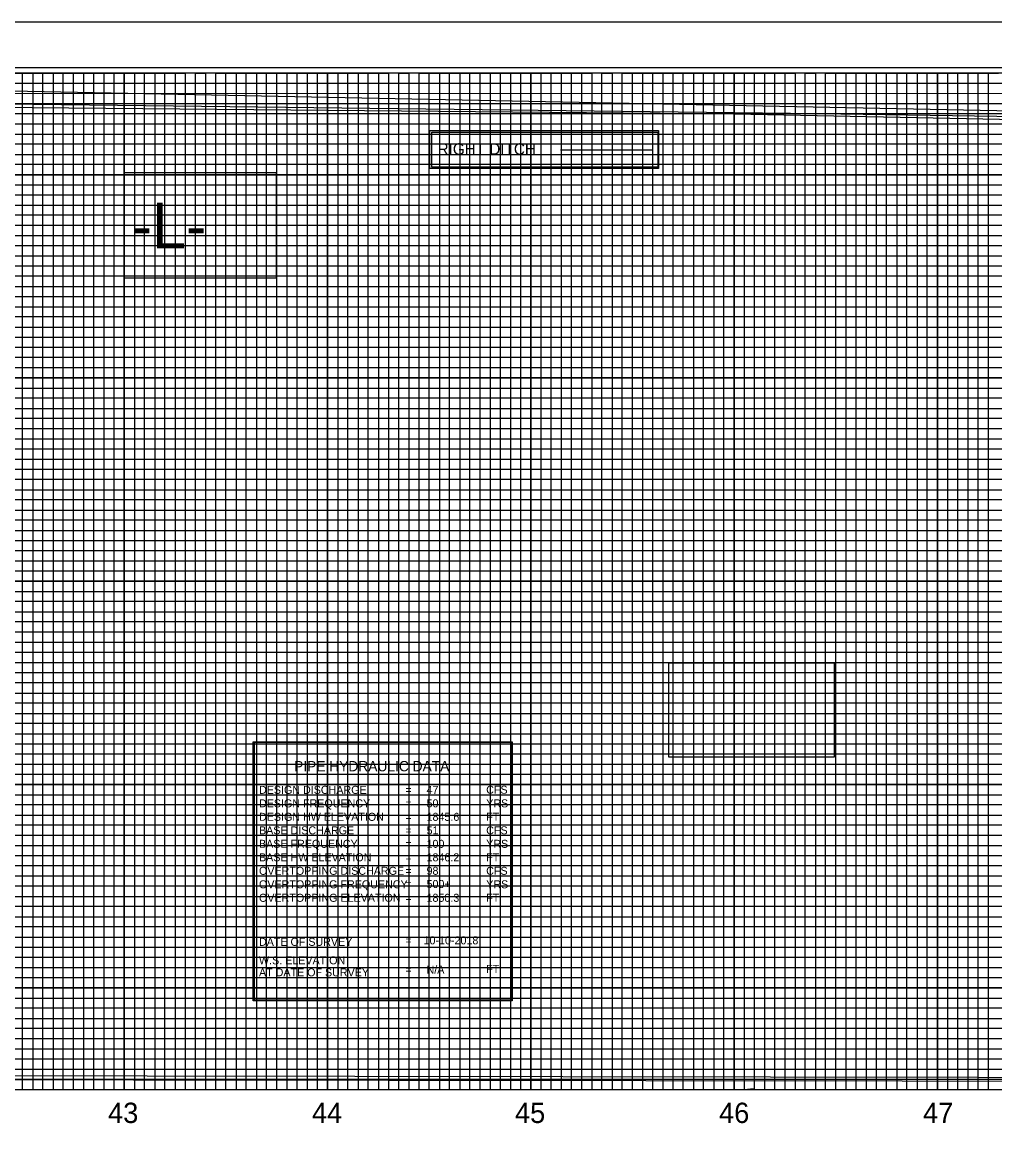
# Model space of a CAD drawing. Extents: x 557032 to 562069, y 513430 to 515874.
# Drawn here: x 557699 to 558178, y 515328 to 515874 of the extents above; entities that cross this region are included whole.
import ezdxf

# ---------------------------------------------------------------- set-up
doc = ezdxf.new("R2010")
doc.units = 0
for name, color, linetype in [('Exist Vertical Profile Horizontal Axis Label Major', 7, 'Continuous'), ('Prop Grid Mask', 7, 'Continuous'), ('Prop PFL Ditch Label CELL', 7, 'Continuous'), ('Prop Vertical Profile Curve Label', 7, 'Continuous'), ('Prop VPI Label', 7, 'Continuous'), ('Scratch_Level_5', 7, 'Continuous'), ('Sheet Cutting Line CELL', 7, 'Continuous'), ('Sheet DOT Grid CELL', 7, 'Continuous'), ('Sheet Layout Profile Border Port 1', 7, 'Continuous'), ('Sheet Plot Border Inside CELL', 7, 'Continuous'), ('Sheet Plot Border Outside CELL', 7, 'Continuous'), ('Sheet Profile CELL', 7, 'Continuous'), ('Sheet Profile Grid Major CELL', 7, 'Continuous'), ('Sheet Profile Grid Middle CELL', 7, 'Continuous'), ('Sheet Profile Grid Minor CELL', 7, 'Continuous')]:
    doc.layers.add(name, color=color, linetype=linetype)

msp = doc.modelspace()

# ---------------------------------------------------------------- linework, layer by layer
at = {"layer": 'Prop Grid Mask'}
msp.add_lwpolyline([(557899.83, 515821.03), (558012.33, 515821.03), (558012.33, 515802.28), (557899.83, 515802.28)], close=True, dxfattribs=at)
at = {"layer": 'Prop PFL Ditch Label CELL'}
for p, q in [((557899.83, 515809.78), (557899.83, 515809.78)), ((557963.99, 515811.54), (558008.99, 515811.54))]:
    msp.add_line(p, q, dxfattribs=at)
at = {"layer": 'Prop Vertical Profile Curve Label'}
for points in [[(557749.44, 515800.34), (557824.2, 515800.34), (557824.2, 515748.39), (557749.44, 515748.39)], [(557749.44, 515800.34), (557824.2, 515800.34), (557824.2, 515748.39), (557749.44, 515748.39)], [(558017.37, 515559.11), (558098.7, 515559.11), (558098.7, 515512.81), (558017.37, 515512.81)], [(557812.9, 515520.28), (557940.3, 515520.28), (557940.3, 515392.88), (557812.9, 515392.88)]]:
    msp.add_lwpolyline(points, close=True, dxfattribs=at)
at = {"layer": 'Prop VPI Label'}
for points in [[(557900.71, 515820.13), (558011.86, 515820.13), (558011.86, 515802.99), (557900.71, 515802.99)], [(557749.44, 515800.34), (557824.2, 515800.34), (557824.2, 515748.39), (557749.44, 515748.39)], [(557813.36, 515393.43), (557939.92, 515393.43), (557939.92, 515520), (557813.36, 515520)]]:
    msp.add_lwpolyline(points, close=True, dxfattribs=at)
at = {"layer": 'Scratch_Level_5'}
msp.add_lwpolyline([(558499.4, 515824.23), (557249.45, 515849.28), (557249.45, 515349.28), (557236.61, 515332.67), (557249.45, 515324.28), (558649.45, 515324.28), (558662.72, 515334.01), (558649.45, 515349.28), (558649.45, 515688.23), (558499.4, 515688.23)], close=True, dxfattribs=at)
for points in [[(558649.42, 515686.42), (558641.97, 515686.42), (558497.02, 515687.96), (558497.02, 515823.15), (558090.9, 515829.21), (557249.42, 515839.17)], [(558649.45, 515682.57), (558492.81, 515683.83), (558490.11, 515820.17), (558049.46, 515829.04), (557249.45, 515836.19)], [(557249.42, 515356.85), (558373.93, 515355.08), (558412.39, 515354.77), (558649.42, 515355.8)], [(557249.45, 515354.68), (558384.27, 515353.2), (558399.94, 515350.88), (558440.57, 515354.03), (558649.45, 515354.48)]]:
    msp.add_lwpolyline(points, dxfattribs=at)
at = {"layer": 'Sheet Cutting Line CELL'}
msp.add_line((558716.45, 515874.28), (557032.45, 515874.28), dxfattribs=at)
at = {"layer": 'Sheet DOT Grid CELL'}
for p, q in [((557699.45, 515349.28), (557699.45, 515849.28)), ((557749.45, 515349.28), (557749.45, 515849.28)), ((557799.45, 515349.28), (557799.45, 515849.28)), ((557849.45, 515349.28), (557849.45, 515849.28)), ((557899.45, 515349.28), (557899.45, 515849.28)), ((557949.45, 515349.28), (557949.45, 515849.28)), ((557999.45, 515349.28), (557999.45, 515849.28)), ((558049.45, 515349.28), (558049.45, 515849.28)), ((558099.45, 515349.28), (558099.45, 515849.28)), ((558149.45, 515349.28), (558149.45, 515849.28)), ((558499.4, 515799.28), (557199.45, 515799.28)), ((558499.4, 515749.28), (557199.45, 515749.28)), ((558499.45, 515699.28), (557199.45, 515699.28)), ((558699.45, 515649.28), (557199.45, 515649.28)), ((558699.45, 515599.28), (557199.45, 515599.28)), ((558699.45, 515549.28), (557199.45, 515549.28)), ((558699.45, 515499.28), (557199.45, 515499.28)), ((558699.45, 515449.28), (557199.45, 515449.28)), ((558699.45, 515399.28), (557199.45, 515399.28))]:
    msp.add_line(p, q, dxfattribs=at)
at = {"layer": 'Sheet Layout Profile Border Port 1'}
msp.add_lwpolyline([(557249.45, 515688.23), (557249.45, 515349.28), (558649.45, 515349.28), (558649.45, 515688.23)], dxfattribs=at)
at = {"layer": 'Sheet Plot Border Inside CELL'}
msp.add_lwpolyline([(557045.45, 514796.73), (558711.95, 514796.73), (558711.95, 515851.83), (557045.45, 515851.83)], close=True, dxfattribs=at)
at = {"layer": 'Sheet Plot Border Outside CELL'}
msp.add_lwpolyline([(557032.45, 514774.28), (558716.45, 514774.28), (558716.45, 515874.28), (557032.45, 515874.28)], close=True, dxfattribs=at)
at = {"layer": 'Sheet Profile CELL'}
msp.add_line((557199.45, 515349.28), (558699.45, 515349.28), dxfattribs=at)
msp.add_lwpolyline([(558699.45, 515849.28), (557199.45, 515849.28), (557199.45, 514799.28), (558699.45, 514799.28)], close=True, dxfattribs=at)
at = {"layer": 'Sheet Profile Grid Major CELL'}
for points in [[(557649.45, 515349.28), (557699.45, 515349.28), (557699.45, 515849.28), (557749.45, 515849.28), (557749.45, 515349.28), (557799.45, 515349.28), (557799.45, 515849.28), (557849.45, 515849.28), (557849.45, 515349.28), (557899.45, 515349.28), (557899.45, 515849.28), (557949.45, 515849.28), (557949.45, 515349.28), (557999.45, 515349.28), (557999.45, 515849.28), (558049.45, 515849.28), (558049.45, 515349.28), (558099.45, 515349.28), (558099.45, 515849.28), (558149.45, 515849.28), (558149.45, 515349.28), (558199.45, 515349.28)], [(557199.45, 515799.28), (558499.45, 515799.28)], [(558499.45, 515749.28), (557199.45, 515749.28), (557199.45, 515699.28), (558499.45, 515699.28)], [(558699.45, 515649.28), (557199.45, 515649.28), (557199.45, 515599.28), (558699.45, 515599.28)], [(558699.45, 515549.28), (557199.45, 515549.28), (557199.45, 515499.28), (558699.45, 515499.28)], [(558699.45, 515449.28), (557199.45, 515449.28), (557199.45, 515449.28), (557199.45, 515399.28), (558699.45, 515399.28)]]:
    msp.add_lwpolyline(points, dxfattribs=at)
at = {"layer": 'Sheet Profile Grid Middle CELL'}
msp.add_line((557199.45, 515824.28), (558499.4, 515824.28), dxfattribs=at)
for points in [[(557674.45, 515349.28), (557724.45, 515349.28), (557724.45, 515849.28), (557774.45, 515849.28), (557774.45, 515349.28), (557824.45, 515349.28), (557824.45, 515349.28), (557824.45, 515849.28), (557874.45, 515849.28), (557874.45, 515349.28), (557924.45, 515349.28), (557924.45, 515849.28), (557974.45, 515849.28), (557974.45, 515349.28), (558024.45, 515349.28), (558024.45, 515849.28), (558074.45, 515849.28), (558074.45, 515349.28), (558124.45, 515349.28), (558124.45, 515849.28), (558174.45, 515849.28), (558174.45, 515349.28), (558224.45, 515349.28)], [(558499.45, 515774.28), (557199.45, 515774.28), (557199.45, 515724.28), (558499.45, 515724.28)], [(558699.45, 515674.28), (557199.45, 515674.28), (557199.45, 515624.28), (558524.45, 515624.28)], [(558699.45, 515574.28), (557199.45, 515574.28), (557199.45, 515524.28), (558699.45, 515524.28)], [(558699.45, 515474.28), (557199.45, 515474.28), (557199.45, 515424.28), (558699.45, 515424.28)], [(558699.45, 515374.28), (557199.45, 515374.28)]]:
    msp.add_lwpolyline(points, dxfattribs=at)
at = {"layer": 'Sheet Profile Grid Minor CELL'}
for p, q in [((557249.45, 515844.28), (558499.45, 515844.28)), ((558499.45, 515839.28), (557249.45, 515838.93)), ((557249.45, 515834.28), (558499.45, 515834.28)), ((558499.4, 515714.28), (557249.45, 515714.28)), ((558499.45, 515709.28), (557249.45, 515709.28)), ((558499.45, 515704.28), (557249.45, 515704.28)), ((557249.45, 515694.28), (558499.45, 515694.28)), ((558499.45, 515689.28), (557249.45, 515689.28)), ((557249.45, 515684.28), (558649.45, 515684.28)), ((558649.45, 515664.28), (557249.45, 515664.28)), ((557249.45, 515659.28), (558649.45, 515659.28)), ((558649.45, 515639.28), (557249.45, 515639.28)), ((557249.45, 515634.28), (558649.45, 515634.28)), ((558649.45, 515614.28), (557249.45, 515614.28)), ((557249.45, 515609.28), (558649.45, 515609.28)), ((558649.45, 515604.28), (557249.45, 515604.28)), ((557249.45, 515594.28), (558649.45, 515594.28)), ((558649.45, 515589.28), (557249.45, 515589.28)), ((557249.45, 515584.28), (558649.45, 515584.28)), ((558649.45, 515579.28), (557249.45, 515579.28)), ((557249.45, 515569.28), (558649.45, 515569.28)), ((558649.45, 515564.28), (557249.45, 515564.28)), ((557249.45, 515559.28), (558649.45, 515559.28)), ((558649.45, 515554.28), (557249.45, 515554.28)), ((557249.45, 515544.28), (558649.45, 515544.28)), ((558649.45, 515539.28), (557249.45, 515539.28)), ((557249.45, 515534.28), (558649.45, 515534.28)), ((558649.45, 515529.28), (557249.45, 515529.28)), ((557249.45, 515519.28), (558649.45, 515519.28)), ((558649.45, 515514.28), (557249.45, 515514.28)), ((557249.45, 515509.28), (558649.45, 515509.28)), ((558649.45, 515504.28), (557249.45, 515504.28)), ((557249.45, 515494.28), (558649.45, 515494.28)), ((558649.45, 515489.28), (557249.45, 515489.28)), ((557249.45, 515484.28), (558649.45, 515484.28)), ((558649.45, 515479.28), (557249.45, 515479.28)), ((557249.45, 515469.28), (558649.45, 515469.28)), ((558649.45, 515464.28), (557249.45, 515464.28)), ((558649.45, 515459.28), (557249.45, 515459.28)), ((558649.45, 515454.28), (557249.45, 515454.28)), ((557249.45, 515444.28), (558649.45, 515444.28)), ((558649.45, 515439.28), (557249.45, 515439.28)), ((557249.45, 515434.28), (558649.45, 515434.28)), ((558649.45, 515429.28), (557249.45, 515429.28)), ((557249.45, 515419.28), (558649.45, 515419.28)), ((558649.45, 515414.28), (557249.45, 515414.28)), ((557249.45, 515409.28), (558649.45, 515409.28)), ((558649.45, 515404.28), (557249.45, 515404.28)), ((557249.45, 515394.28), (558649.45, 515394.28)), ((558649.45, 515389.28), (557249.45, 515389.28)), ((557249.45, 515384.28), (558649.45, 515384.28)), ((558649.45, 515379.28), (557249.45, 515379.28)), ((557249.45, 515369.28), (558649.45, 515369.28)), ((558649.45, 515364.28), (557249.45, 515364.28)), ((557249.45, 515359.28), (558649.45, 515359.28))]:
    msp.add_line(p, q, dxfattribs=at)
for points in [[(557694.45, 515849.28), (557704.45, 515849.28), (557704.45, 515349.28), (557709.45, 515349.28), (557709.45, 515849.28), (557714.45, 515849.28), (557714.45, 515349.28), (557719.45, 515349.28), (557719.45, 515849.28), (557729.45, 515849.28), (557729.45, 515349.28), (557734.45, 515349.28), (557734.45, 515849.28), (557739.45, 515849.28), (557739.45, 515349.28), (557744.45, 515349.28), (557744.45, 515849.28), (557754.45, 515849.28), (557754.45, 515349.28), (557759.45, 515349.28), (557759.45, 515849.28), (557764.45, 515849.28), (557764.45, 515349.28), (557769.45, 515349.28), (557769.45, 515849.28), (557779.45, 515849.28)], [(557779.45, 515849.28), (557779.45, 515349.28), (557784.45, 515349.28), (557784.45, 515849.28), (557789.45, 515849.28), (557789.45, 515349.28), (557794.45, 515349.28), (557794.45, 515849.28), (557804.45, 515849.28), (557804.45, 515349.28), (557809.45, 515349.28), (557809.45, 515849.28), (557814.45, 515849.28), (557814.45, 515349.28), (557819.45, 515349.28), (557819.45, 515849.28), (557829.45, 515849.28), (557829.45, 515349.28), (557834.45, 515349.28), (557834.45, 515849.28), (557839.45, 515849.28), (557839.45, 515349.28), (557844.45, 515349.28), (557844.45, 515849.28), (557854.45, 515849.28), (557854.45, 515349.28), (557859.45, 515349.28), (557859.45, 515849.28), (557864.45, 515849.28), (557864.45, 515349.28), (557869.45, 515349.28), (557869.45, 515849.28), (557879.45, 515849.28), (557879.45, 515349.28), (557884.45, 515349.28), (557884.45, 515849.28), (557889.45, 515849.28), (557889.45, 515349.28), (557894.45, 515349.28), (557894.45, 515849.28), (557904.45, 515849.28), (557904.45, 515349.28), (557904.45, 515349.28), (557909.45, 515349.28), (557909.45, 515849.28), (557914.45, 515849.28), (557914.45, 515349.28), (557919.45, 515349.28), (557919.45, 515849.28), (557929.45, 515849.28), (557929.45, 515349.28), (557934.45, 515349.28), (557934.45, 515849.28), (557939.45, 515849.28), (557939.45, 515349.28), (557944.45, 515349.28), (557944.45, 515849.28), (557954.45, 515849.28), (557954.45, 515349.28), (557959.45, 515349.28), (557959.45, 515849.28), (557964.45, 515849.28), (557964.45, 515349.28), (557969.45, 515349.28), (557969.45, 515849.28), (557979.45, 515849.28), (557979.45, 515349.28), (557984.45, 515349.28), (557984.45, 515849.28), (557989.45, 515849.28), (557989.45, 515349.28), (557994.45, 515349.28), (557994.45, 515849.28), (558004.45, 515849.28), (558004.45, 515349.28), (558009.45, 515349.28), (558009.45, 515849.28), (558014.45, 515849.28), (558014.45, 515349.28), (558019.45, 515349.28), (558019.45, 515849.28), (558029.45, 515849.28), (558029.45, 515349.28), (558034.45, 515349.28), (558034.45, 515849.28), (558039.45, 515849.28), (558039.45, 515349.28), (558044.45, 515349.28), (558044.45, 515849.28), (558054.45, 515849.28), (558054.45, 515349.28), (558059.15, 515349.83), (558059.45, 515349.28), (558059.45, 515849.28), (558064.45, 515849.28), (558064.45, 515349.28), (558069.45, 515349.28), (558069.45, 515849.28), (558079.45, 515849.28), (558079.45, 515349.28), (558084.45, 515349.28)], [(558084.45, 515349.28), (558084.45, 515849.28), (558089.45, 515849.28), (558089.45, 515349.28), (558094.45, 515349.28), (558094.45, 515849.28), (558104.45, 515849.28), (558104.45, 515349.28), (558109.45, 515349.28), (558109.45, 515849.28), (558114.45, 515849.28), (558114.45, 515349.28), (558119.45, 515349.28), (558119.45, 515849.28), (558129.45, 515849.28), (558129.45, 515349.28), (558134.45, 515349.28), (558134.45, 515849.28), (558139.45, 515849.28), (558139.45, 515349.28), (558144.45, 515349.28), (558144.45, 515849.28), (558154.45, 515849.28), (558154.45, 515349.28), (558159.45, 515349.28), (558159.45, 515849.28), (558164.45, 515849.28), (558164.45, 515349.28), (558169.45, 515349.28), (558169.45, 515849.28), (558179.45, 515849.28)], [(558499.45, 515829.28), (557249.45, 515829.28), (557249.45, 515819.28), (558499.45, 515819.28)], [(558499.4, 515814.28), (557249.45, 515814.28), (557249.45, 515809.28), (558499.45, 515809.28)], [(558499.45, 515804.28), (557249.45, 515804.28), (557249.45, 515794.28), (558499.45, 515794.28)], [(558499.45, 515789.28), (557249.45, 515789.28), (557249.45, 515784.28), (558499.45, 515784.28)], [(558499.45, 515779.28), (557249.45, 515779.28), (557249.45, 515769.28), (558499.45, 515769.28)], [(558499.45, 515764.28), (557249.45, 515764.28), (557249.45, 515759.28), (558499.45, 515759.28)], [(558499.45, 515754.28), (557249.45, 515754.28), (557249.45, 515744.28), (558499.45, 515744.28)], [(558499.45, 515739.18), (557249.55, 515739.18), (557249.55, 515734.28), (558499.45, 515734.28)], [(558499.45, 515729.28), (557249.45, 515729.28), (557249.45, 515719.28), (558499.45, 515719.28)], [(558649.45, 515679.28), (557249.45, 515679.28), (557249.45, 515669.28), (558649.45, 515669.28)], [(558649.45, 515654.28), (557249.45, 515654.28), (557249.45, 515644.28), (558649.45, 515644.28)], [(558649.45, 515629.28), (557249.45, 515629.28), (557249.45, 515619.28), (558649.45, 515619.28)], [(558649.45, 515354.28), (557249.45, 515354.28)]]:
    msp.add_lwpolyline(points, dxfattribs=at)

# ---------------------------------------------------------------- texts
at = {"layer": 'Exist Vertical Profile Horizontal Axis Label Major'}
for s, p in [('43', (557741.46, 515332.81)), ('44', (557841.76, 515332.81)), ('45', (557941.65, 515332.81)), ('46', (558042.04, 515332.81)), ('47', (558142.39, 515332.81))]:
    msp.add_text(s, height=10, dxfattribs=at).set_placement(p)
at = {"layer": 'Prop PFL Ditch Label CELL'}
msp.add_text('RIGHT DITCH', height=5.6138, dxfattribs=at).set_placement((557903.58, 515809.1))
at = {"layer": 'Prop Vertical Profile Curve Label'}
msp.add_text('-L-', height=22.5, dxfattribs=at).set_placement((557753.01, 515763))
at = {"layer": 'Prop VPI Label'}
for s, height, p in [('PIPE HYDRAULIC DATA', 5.0625, (557832.99, 515505.79)), ('DESIGN DISCHARGE', 3.9375, (557815.72, 515494.71)), ('=     47', 3.937, (557887.76, 515494.71)), ('CFS', 3.937, (557927.49, 515494.77)), ('DESIGN FREQUENCY', 3.9375, (557815.72, 515488.07)), ('=     50', 3.937, (557887.76, 515488.07)), ('YRS', 3.937, (557927.49, 515488.07)), ('DESIGN HW ELEVATION', 3.9375, (557815.72, 515481.44)), ('=     1845.6', 3.9375, (557887.76, 515481.44)), ('FT', 3.937, (557927.49, 515481.44)), ('BASE DISCHARGE', 3.9375, (557815.72, 515474.8)), ('=     51', 3.937, (557887.76, 515474.8)), ('CFS', 3.937, (557927.49, 515474.8)), ('BASE FREQUENCY', 3.9375, (557815.72, 515468.16)), ('=     100', 3.937, (557887.76, 515468.16)), ('YRS', 3.937, (557927.49, 515468.16)), ('BASE HW ELEVATION', 3.9375, (557815.72, 515461.52)), ('=     1846.2', 3.9375, (557887.76, 515461.52)), ('FT', 3.937, (557927.49, 515461.52)), ('OVERTOPPING DISCHARGE', 3.9375, (557815.72, 515454.89)), ('=     98', 3.937, (557887.76, 515454.89)), ('CFS', 3.937, (557927.49, 515454.89)), ('OVERTOPPING FREQUENCY', 3.9375, (557815.72, 515448.25)), ('=     500+', 3.937, (557887.76, 515448.41)), ('YRS', 3.937, (557927.49, 515448.25)), ('OVERTOPPING ELEVATION', 3.9375, (557815.72, 515441.61)), ('=     1850.3', 3.9374, (557887.76, 515441.61)), ('FT', 3.937, (557927.49, 515441.61)), ('=    10-10-2018', 3.9375, (557887.76, 515420.69)), ('DATE OF SURVEY', 3.9375, (557815.72, 515419.95)), ('W.S. ELEVATION', 3.9375, (557815.72, 515410.84)), ('AT DATE OF SURVEY', 3.9375, (557815.72, 515404.94)), ('=     N/A', 3.937, (557887.76, 515406.31)), ('FT', 3.937, (557927.49, 515406.65))]:
    msp.add_text(s, height=height, dxfattribs=at).set_placement(p)

doc.saveas('drawing.dxf')
